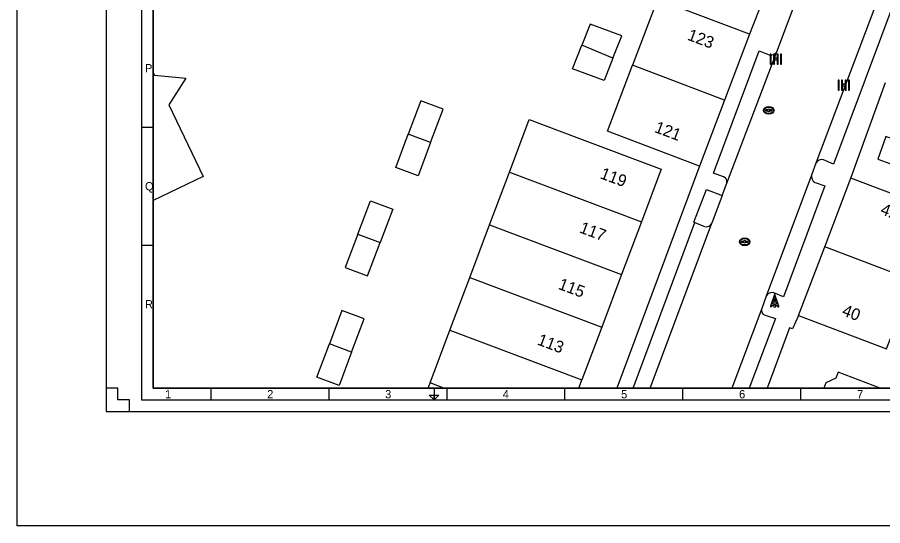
# Model space of a CAD drawing. Extents: x 192664 to 192925, y 446334 to 446521.
# Drawn here: x 192664.2 to 192737.6, y 446333.9 to 446377 of the extents above; entities that cross this region are included whole.
import ezdxf

# ---------------------------------------------------------------- set-up
doc = ezdxf.new("R2010")
doc.units = 0
for name, color, linetype in [('( Toegevoegd 29-11-2021 14_41_42) wegdeel vlak', 7, 'Continuous'), ('1010 viewport', 7, 'Continuous'), ('bovenleidingmast', 7, 'Continuous'), ('huisnummerreeks BGT', 7, 'Continuous'), ('inspectie-   rioolput', 7, 'Continuous'), ('kant open verharding', 7, 'Continuous'), ('kant verharding', 7, 'Continuous'), ('kolk', 7, 'Continuous'), ('pand op maaiveld vlak', 7, 'Continuous'), ('verkeerseiland - berm', 7, 'Continuous'), ('X-XX-AL-TEKENBLAD-S', 7, 'Continuous'), ('X-XX-AL-TEKENBLAD_KADER-G', 7, 'Continuous')]:
    doc.layers.add(name, color=color, linetype=linetype)

msp = doc.modelspace()

# ---------------------------------------------------------------- linework, layer by layer
at = {"layer": '( Toegevoegd 29-11-2021 14_41_42) wegdeel vlak'}
for p, q in [((192734.872, 446363.349), (192737.803, 446371.456)), ((192731.919, 446364.598), (192731.529, 446363.599)), ((192727.683, 446353.343), (192727.316, 446352.308))]:
    msp.add_line(p, q, dxfattribs=at)
msp.add_lwpolyline([(192730.442, 446351.705), (192729.93, 446350.568), (192729.687, 446350.658), (192727.788, 446345.556)], dxfattribs=at)
at = {"layer": '1010 viewport'}
msp.add_lwpolyline([(192675.743, 446509.756), (192860.643, 446509.756), (192860.643, 446345.556), (192675.743, 446345.556)], close=True, dxfattribs=at)
at = {"layer": 'bovenleidingmast'}
for p, q in [((192728.402, 446353.473), (192728.061, 446352.5)), ((192728.761, 446352.5), (192728.42, 446353.473))]:
    msp.add_line(p, q, dxfattribs=at)
msp.add_lwpolyline([(192728.533, 446352.85), (192728.603, 446352.65), (192728.219, 446352.65), (192728.289, 446352.85)], close=True, dxfattribs=at)
for points in [[(192728.42, 446353.17), (192728.498, 446352.95), (192728.324, 446352.95), (192728.402, 446353.17)], [(192728.155, 446352.467), (192728.184, 446352.55), (192728.324, 446352.55)], [(192728.498, 446352.55), (192728.638, 446352.55), (192728.667, 446352.467)]]:
    msp.add_lwpolyline(points, dxfattribs=at)
for centre, radius, start, end in [((192728.411, 446353.47), 0.01, 19.29005, 160.70995), ((192728.411, 446353.167), 0.01, 19.29005, 160.70995), ((192728.108, 446352.483), 0.05, 160.70995, 340.70995), ((192728.411, 446352.5), 0.1, 0, 180), ((192728.411, 446352.5), 0.1, 180, 0), ((192728.411, 446352.5), 0.1, 30, 150), ((192728.714, 446352.483), 0.05, 199.29005, 19.29005)]:
    msp.add_arc(centre, radius, start, end, dxfattribs=at)
at = {"layer": 'inspectie-   rioolput'}
for p, q in [((192727.825, 446369.123), (192727.668, 446369.123)), ((192727.668, 446369.049), (192727.825, 446369.049)), ((192728.168, 446369.123), (192728.011, 446369.123)), ((192728.011, 446369.049), (192728.168, 446369.049)), ((192725.782, 446357.986), (192725.625, 446357.986)), ((192725.625, 446357.911), (192725.782, 446357.911)), ((192726.125, 446357.986), (192725.968, 446357.986)), ((192725.968, 446357.911), (192726.125, 446357.911))]:
    msp.add_line(p, q, dxfattribs=at)
for centre, radius, start, end in [((192727.668, 446369.086), 0.0375, 90, 270), ((192727.918, 446369.086), 0.1, 0, 180), ((192727.918, 446369.086), 0.1, 157.97569, 180), ((192727.918, 446369.086), 0.1, 180, 202.02431), ((192727.918, 446369.086), 0.1, 180, 0), ((192727.918, 446369.086), 0.1, 0, 22.02431), ((192727.918, 446369.086), 0.1, 337.97569, 0), ((192728.168, 446369.086), 0.0375, 270, 90), ((192725.625, 446357.948), 0.0375, 90, 270), ((192725.875, 446357.948), 0.1, 0, 180), ((192725.875, 446357.948), 0.1, 157.97569, 180), ((192725.875, 446357.948), 0.1, 180, 202.02431), ((192725.875, 446357.948), 0.1, 180, 0), ((192725.875, 446357.948), 0.1, 0, 22.02431), ((192725.875, 446357.948), 0.1, 337.97569, 0), ((192726.125, 446357.948), 0.0375, 270, 90)]:
    msp.add_arc(centre, radius, start, end, dxfattribs=at)
for centre, major_axis, ratio in [((192727.918, 446369.086), (-0.442, 0), 0.73911), ((192727.918, 446369.086), (-0.392, 0), 0.689655), ((192725.875, 446357.948), (-0.442, 0), 0.73911), ((192725.875, 446357.948), (-0.392, 0), 0.689655)]:
    msp.add_ellipse(centre, major_axis=major_axis, ratio=ratio, dxfattribs=at)
at = {"layer": 'kant open verharding'}
for p, q in [((192728.589, 446374.052), (192734.543, 446389.88)), ((192729.467, 446383.724), (192726.296, 446375.548)), ((192722.057, 446364.352), (192715.03, 446345.556)), ((192723.966, 446361.859), (192724.36, 446362.912))]:
    msp.add_line(p, q, dxfattribs=at)
at = {"layer": 'kant verharding'}
for p, q in [((192737.657, 446379.855), (192731.919, 446364.598)), ((192724.36, 446362.912), (192728.589, 446374.052)), ((192731.529, 446363.599), (192727.683, 446353.343)), ((192716.41, 446345.556), (192721.66, 446359.568)), ((192717.853, 446345.556), (192723.089, 446359.513)), ((192727.316, 446352.308), (192724.781, 446345.556))]:
    msp.add_line(p, q, dxfattribs=at)
for points in [[(192738.766, 446378.901), (192733.402, 446364.531), (192732.55, 446364.886)], [(192724.074, 446363.455), (192723.221, 446363.769), (192727.106, 446374.125), (192727.941, 446373.798)], [(192731.835, 446362.98), (192732.679, 446362.694), (192729.153, 446353.29), (192728.352, 446353.623)], [(192727.621, 446351.736), (192728.481, 446351.454), (192726.249, 446345.556)]]:
    msp.add_lwpolyline(points, dxfattribs=at)
for centre, radius, start, end in [((192728.122, 446374.291), 0.525, 249.84982, 332.95809), ((192732.4, 446364.38), 0.528, 73.44286, 155.6228), ((192723.936, 446363.036), 0.441, 343.74269, 71.80917), ((192732.117, 446363.505), 0.596, 170.88809, 241.72249), ((192728.181, 446353.093), 0.557, 72.07398, 153.34806), ((192727.75, 446352.172), 0.455, 162.6544, 253.48018)]:
    msp.add_arc(centre, radius, start, end, dxfattribs=at)
at = {"layer": 'kolk'}
for points in [[(192728.113, 446373.423), (192728.113, 446373.848), (192728.028, 446373.848), (192728.028, 446373.423), (192728.028, 446372.998), (192728.113, 446372.998)], [(192728.411, 446373.423), (192728.411, 446373.848), (192728.326, 446373.848), (192728.326, 446373.423), (192728.326, 446372.998), (192728.411, 446372.998)], [(192728.708, 446373.423), (192728.708, 446373.848), (192728.623, 446373.848), (192728.623, 446373.423), (192728.623, 446372.998), (192728.708, 446372.998)], [(192729.006, 446373.423), (192729.006, 446373.848), (192728.921, 446373.848), (192728.921, 446373.423), (192728.921, 446372.998), (192729.006, 446372.998)], [(192733.877, 446371.226), (192733.877, 446371.651), (192733.792, 446371.651), (192733.792, 446371.226), (192733.792, 446370.801), (192733.877, 446370.801)], [(192734.175, 446371.226), (192734.175, 446371.651), (192734.09, 446371.651), (192734.09, 446371.226), (192734.09, 446370.801), (192734.175, 446370.801)], [(192734.472, 446371.226), (192734.472, 446371.651), (192734.387, 446371.651), (192734.387, 446371.226), (192734.387, 446370.801), (192734.472, 446370.801)], [(192734.77, 446371.226), (192734.77, 446371.651), (192734.685, 446371.651), (192734.685, 446371.226), (192734.685, 446370.801), (192734.77, 446370.801)]]:
    msp.add_lwpolyline(points, close=True, dxfattribs=at)
for centre, start, end in [((192728.517, 446373.423), 0, 180), ((192728.517, 446373.423), 180, 0), ((192734.281, 446371.226), 0, 180), ((192734.281, 446371.226), 180, 0)]:
    msp.add_arc(centre, 0.1, start, end, dxfattribs=at)
at = {"layer": 'pand op maaiveld vlak'}
for p, q in [((192726.296, 446375.548), (192724.176, 446369.95)), ((192714.709, 446373.499), (192712.083, 446374.618)), ((192724.176, 446369.95), (192716.363, 446372.909)), ((192724.176, 446369.95), (192722.057, 446364.352)), ((192699.252, 446366.354), (192697.362, 446367.067)), ((192704.254, 446359.382), (192705.936, 446363.845)), ((192705.936, 446363.845), (192717.127, 446359.628)), ((192732.657, 446357.527), (192734.872, 446363.349)), ((192702.572, 446354.92), (192704.254, 446359.382)), ((192704.254, 446359.382), (192715.445, 446355.165)), ((192717.127, 446359.628), (192715.445, 446355.165)), ((192693.087, 446358.59), (192694.977, 446357.877)), ((192730.442, 446351.705), (192732.657, 446357.527)), ((192740.119, 446354.688), (192732.657, 446357.527)), ((192715.445, 446355.165), (192713.764, 446350.703)), ((192700.89, 446350.458), (192702.572, 446354.92)), ((192702.572, 446354.92), (192713.764, 446350.703)), ((192713.764, 446350.703), (192712.083, 446346.24)), ((192699.208, 446345.995), (192700.89, 446350.458)), ((192700.89, 446350.458), (192712.083, 446346.24)), ((192692.56, 446348.6), (192690.67, 446349.313)), ((192711.825, 446345.556), (192712.083, 446346.24)), ((192699.042, 446345.556), (192699.208, 446345.995)), ((192700.374, 446345.556), (192699.208, 446345.995))]:
    msp.add_line(p, q, dxfattribs=at)
for points in [[(192726.296, 446375.548), (192718.482, 446378.507), (192716.363, 446372.909)], [(192714.709, 446373.499), (192715.452, 446375.385), (192712.777, 446376.376), (192712.083, 446374.618)], [(192714.709, 446373.499), (192713.965, 446371.612), (192711.293, 446372.613), (192712.083, 446374.618)], [(192722.057, 446364.352), (192714.243, 446367.31), (192716.363, 446372.909)], [(192675.743, 446372.272), (192675.837, 446372.077), (192678.502, 446371.807), (192677.062, 446369.552), (192679.976, 446363.486), (192675.743, 446361.453)], [(192699.252, 446366.354), (192700.317, 446369.18), (192698.427, 446369.892), (192697.362, 446367.067)], [(192705.936, 446363.845), (192707.619, 446368.308), (192711.656, 446366.786), (192718.809, 446364.09), (192717.127, 446359.628)], [(192699.252, 446366.354), (192698.186, 446363.528), (192696.296, 446364.241), (192697.362, 446367.067)], [(192737.844, 446366.858), (192737.159, 446364.958), (192740, 446363.934), (192740.685, 446365.834), (192737.844, 446366.858)], [(192740.119, 446354.688), (192742.334, 446360.51), (192734.872, 446363.349)], [(192693.087, 446358.59), (192694.152, 446361.415), (192696.042, 446360.703), (192694.977, 446357.877)], [(192693.087, 446358.59), (192692.021, 446355.764), (192693.911, 446355.051), (192694.977, 446357.877)], [(192730.442, 446351.705), (192737.904, 446348.866), (192740.119, 446354.688)], [(192692.56, 446348.6), (192693.625, 446351.426), (192691.735, 446352.138), (192690.67, 446349.313)], [(192692.56, 446348.6), (192691.495, 446345.774), (192689.604, 446346.487), (192690.67, 446349.313)], [(192737.358, 446345.556), (192733.786, 446346.892), (192733.598, 446346.389), (192732.755, 446345.984), (192732.595, 446345.556)]]:
    msp.add_lwpolyline(points, dxfattribs=at)
at = {"layer": 'verkeerseiland - berm'}
for p, q in [((192723.966, 446361.859), (192723.089, 446359.513)), ((192721.66, 446359.568), (192722.478, 446359.251))]:
    msp.add_line(p, q, dxfattribs=at)
msp.add_lwpolyline([(192721.66, 446359.568), (192721.566, 446359.604), (192722.629, 446362.391), (192723.966, 446361.859)], dxfattribs=at)
for centre, radius, start, end in [((192722.638, 446359.722), 0.497, 251.25926, 335.16056), ((192725.113, 446345.079), 0.478, 85.41236, 94.58764)]:
    msp.add_arc(centre, radius, start, end, dxfattribs=at)
at = {"layer": 'X-XX-AL-TEKENBLAD-S'}
for p, q in [((192671.743, 446511.756), (192671.743, 446343.556)), ((192674.743, 446510.756), (192674.743, 446344.556)), ((192674.743, 446367.656), (192675.743, 446367.656)), ((192674.743, 446357.656), (192675.743, 446357.656)), ((192680.643, 446344.556), (192680.643, 446345.556)), ((192690.643, 446344.556), (192690.643, 446345.556)), ((192699.543, 446345.556), (192699.543, 446344.556)), ((192700.643, 446344.556), (192700.643, 446345.556)), ((192710.643, 446344.556), (192710.643, 446345.556)), ((192720.643, 446344.556), (192720.643, 446345.556)), ((192730.643, 446344.556), (192730.643, 446345.556)), ((192699.543, 446344.956), (192699.543, 446344.556)), ((192699.543, 446344.556), (192699.543, 446344.956)), ((192674.743, 446344.556), (192908.543, 446344.556)), ((192671.743, 446343.556), (192909.543, 446343.556))]:
    msp.add_line(p, q, dxfattribs=at)
msp.add_lwpolyline([(192675.743, 446345.556), (192907.543, 446345.556), (192907.543, 446509.756), (192675.743, 446509.756)], close=True, dxfattribs=at)
for points in [[(192671.743, 446345.556), (192671.743, 446343.556), (192673.743, 446343.556), (192673.743, 446344.556), (192672.743, 446344.556), (192672.743, 446345.556), (192671.743, 446345.556)], [(192699.543, 446344.556), (192699.143, 446344.956), (192699.543, 446344.956)], [(192699.543, 446344.956), (192699.943, 446344.956), (192699.543, 446344.556)]]:
    msp.add_lwpolyline(points, dxfattribs=at)
at = {"layer": 'X-XX-AL-TEKENBLAD_KADER-G'}
msp.add_lwpolyline([(192664.22, 446520.974), (192925.029, 446520.974), (192925.029, 446333.894), (192664.22, 446333.894)], close=True, dxfattribs=at)

# ---------------------------------------------------------------- texts
at = {"layer": 'huisnummerreeks BGT'}
for s, rotation, p in [('123', 339.3, (192720.947, 446375.084)), ('121', 339.3, (192718.161, 446367.266)), ('119', 339.4, (192713.551, 446363.347)), ('42', 339.2, (192737.312, 446360.322)), ('117', 339.4, (192711.799, 446358.757)), ('115', 339.4, (192709.999, 446353.974)), ('40', 339.2, (192734.051, 446351.744)), ('113', 339.4, (192708.224, 446349.261))]:
    msp.add_text(s, height=1, rotation=rotation, dxfattribs=at).set_placement(p)
at = {"layer": 'X-XX-AL-TEKENBLAD-S'}
for s, p in [('P', (192675.043, 446372.306)), ('Q', (192675.043, 446362.306)), ('R', (192675.043, 446352.306)), ('1', (192676.745, 446344.685)), ('2', (192685.399, 446344.685)), ('3', (192695.398, 446344.685)), ('4', (192705.364, 446344.685)), ('5', (192715.399, 446344.685)), ('6', (192725.399, 446344.685)), ('7', (192735.399, 446344.685))]:
    msp.add_text(s, height=0.7, dxfattribs=at).set_placement(p)

doc.saveas('drawing.dxf')
